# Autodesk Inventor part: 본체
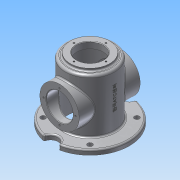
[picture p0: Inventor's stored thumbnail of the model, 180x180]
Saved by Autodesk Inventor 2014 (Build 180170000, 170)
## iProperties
Created: 2018-04
Part Number: 본체
Material: 알루미늄 6061
Document SubType Name: Modeling
Designer: user
Density: 2.71 g/cm^3
Appearance: 알루미늄 - 평지
Mass: 1152.24 g
Surface Area: 1202.61 cm^2
Volume: 425.181 cm^3
Author: user
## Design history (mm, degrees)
sketch "스케치1"
  geometry: C1 r 50 at (0, 0); 1 further point
  constraints: 1 centre point, 1 coincident
  dimensions: "d0" = 100 diameter of C1
extrude "돌출1" new body sketch "스케치1" distance "d1" = 128; taper "d2" = 0 deg
feature "쉘1" dims "d3" = 8, "d4" = 5
sketch "스케치2"
  geometry: C1 r 50 at (0, 0) reference; C2 r 40 at (0, 0)
  constraints: 1 centre point, 1 coincident
  dimensions: "d5" = 80 diameter of C2
extrude "돌출2" join sketch "스케치2" distance "d6" = 5; taper "d7" = 0 deg
sketch "스케치3"
  geometry: C1 r 40 at (0, 0) reference; C2 r 27 at (0, 0)
  constraints: 1 centre point, 1 coincident
  dimensions: "d8" = 54 diameter of C2
extrude "돌출3" cut sketch "스케치3" distance "d9" = 13; taper "d10" = 0 deg
node "작업 평면1"
sketch "스케치4"
  geometry: L1 (0, 0)-(-47.73, 47.73); L2 (0, 0)-(67.5, 0); C1 r 45 at (0, 0) reference; C2 r 50 at (0, 0) reference; C3 r 45 at (0, 0) reference; C4 r 50 at (0, 0) reference; C5 r 5 at (-47.73, 47.73); C6 r 5 at (-47.73, -47.73); C7 r 5 at (47.73, -47.73); C8 r 5 at (47.73, 47.73); A1 r 15 centre (80, 0) between (78.594, 14.934) and (78.594, -14.934); A2 r 15 centre (-80, 0) between (-78.594, -14.934) and (-78.594, 14.934); A3 r 80 centre (0, 0) between (-78.594, -14.934) and (78.594, -14.934); A4 r 80 centre (0, 0) between (78.594, 14.934) and (-78.594, 14.934); 1 further point
  constraints: 8 centre point, 8 point on circle, 4 end point, 2 coincident, 1 equal length, 1 horizontal, 9 other
  dimensions: "d13" = 30 diameter of A1; "d14" = 30 diameter of A2; "d15" = 67.5 distance of L1.start L1.end; "d16" = 135 deg angle of L2 L1; "d17" = 10 diameter of C5; "d20" = 360 deg dimension on L1.start C5.centre (derived); "d22" = 80 radius of A4; "d23" = 80 radius of A3; "d24" = 0 distance from line of A1.centre L2; "d25" = 56.56854 distance from line of A1.centre L1; "d26" = 14.93394 distance from line of A2.end L2; "d27" = 14.93394 distance from line of A2.start L2
extrude "돌출4" join sketch "스케치4" distance "d28" = 10; taper "d29" = 0 deg
node "작업 평면2"
sketch "스케치5"
  geometry: C1 r 40 at (0, 68); 1 further point
  constraints: 1 centre point, 1 vertical alignment
  dimensions: "d31" = 80 diameter of C1; "d32" = 68 distance of point (0, 0) C1.centre
extrude "돌출5" join sketch "스케치5" stored distance "d33" = 80 (= d31); taper "d34" = 0 deg
sketch "스케치6"
  geometry: C1 r 40 at (0, 0) reference; C2 r 27 at (0, 0); 1 further point
  constraints: 1 centre point, 1 coincident
  dimensions: "d35" = 54 diameter of C2
extrude "돌출6" cut sketch "스케치6" distance "d36" = 100; taper "d37" = 0 deg
sketch "스케치7"
  geometry: C1 r 27 at (0, 0) reference; 5 further points
  constraints: 1 horizontal alignment, 5 other
  dimensions: "d38" = 32.5 distance of C1.centre point (32.5, 0); "d41" = 360 deg dimension on C1.centre point (32.5, 0) (derived)
hole "구멍1" sketch "스케치7" at (32.5, 0), (0, 32.5), (-32.5, 0), (0, -32.5) diameter "d43" = 3.242; stored, may be unused: countersink angle "d47" = 90 deg, drill point angle "d49" = 118 deg; dims "d44" = 8, "d45" = 4, "d46" = 2, "d48" = 10
sketch "스케치8"
  geometry: C1 r 27 at (0, 0) reference; 4 further points
  constraints: 1 vertical alignment, 5 other
  dimensions: "d50" = 32.5 distance of point (0, 32.5) C1.centre; "d53" = 360 deg dimension on C1.centre point (0, 32.5) (derived)
hole "구멍2" sketch "스케치8" at (0, 32.5), (-32.5, 0), (0, -32.5), (32.5, 0) diameter "d55" = 3.242; stored, may be unused: countersink angle "d59" = 90 deg, drill point angle "d61" = 118 deg; dims "d56" = 8, "d57" = 4, "d58" = 2, "d60" = 10
node "작업 평면3"
sketch "스케치9"
  geometry: L1 (-78.594, 8)-(78.594, 8) reference; 2 further points
  constraints: 1 vertical alignment, 1 other
  dimensions: "d63" = 70 distance from line of point (0, 78) L1
feature "엠보싱1" sketch "스케치9" dims "d1" = 128, "d64" = 0.5, "d65" = 0
fillet "모깎기1" dims "d66" = 3
fillet "모깎기2" dims "d67" = 3
fillet "모깎기3" dims "d68" = 3
fillet "모깎기4" dims "d69" = 3
fillet "모깎기5" dims "d70" = 5
fillet "모깎기6" dims "d71" = 3
fillet "모깎기7" dims "d72" = 3
chamfer "모따기1" distance "d73" = 1; stored, may be unused: second distance "d74" = 2, angle "d75" = 45 deg
chamfer "모따기2" distance "d76" = 1; stored, may be unused: second distance "d77" = 2, angle "d78" = 45 deg
fillet "모깎기8" dims "d79" = 3
fillet "모깎기9" dims "d80" = 3
node "솔리드1"
mirror "대칭1"
mirror "대칭2"
node "절단 모서리 투영1"
node "절단 모서리 투영2"
other parameters: "d11" = -8, "d30" = 62
